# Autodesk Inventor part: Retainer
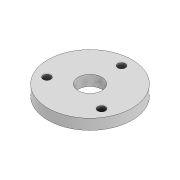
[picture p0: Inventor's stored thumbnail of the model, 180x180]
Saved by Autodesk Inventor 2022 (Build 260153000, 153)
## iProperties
Created: 2019-03
Part Number: Retainer
Material: Generic
Document SubType Name: Modeling
Designer: LENOVO-CADCIM
Density: 1 g/cm^3
Appearance: Default
Author: LENOVO-CADCIM
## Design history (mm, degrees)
sketch "Sketch1" dims "d1" = 150
  geometry: C1 r 100 at (0, 0); 3 further points
  constraints: 2 coincident, 1 centre point, 1 vertical alignment, 2 other
  dimensions: "d0" = 200 diameter of C1
extrude "Extrusion1" new body sketch "Sketch1" stored distance "d2" = 25; taper "d3" = 0 deg
sketch "Sketch2" dims "d4" = 150
  geometry: 3 further points
  constraints: 1 coincident, 1 vertical alignment, 2 other
hole "Hole1" sketch "Sketch2" at (0, 75) diameter "d5" = 18.376; stored, may be unused: countersink angle "d9" = 90 deg, drill point angle "d11" = 118 deg; dims "d6" = 40, "d7" = 4.4, "d8" = 2, "d10" = 47.3
pattern_circular "Circular Pattern1" dims angle "d13" = 360 deg
sketch "Sketch3"
  geometry: C1 r 28 at (0, 0); 1 further point
  constraints: 1 centre point, 1 coincident
  dimensions: "d15" = 56 diameter of C1
extrude "Extrusion2" cut sketch "Sketch3" distance "d16" = 25; taper "d17" = 0 deg
body "Solid1"
